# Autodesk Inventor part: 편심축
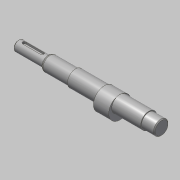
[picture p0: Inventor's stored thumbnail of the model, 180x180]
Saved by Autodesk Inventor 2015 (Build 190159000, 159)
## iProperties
Created: 2017-08
Part Number: 편심축
Material: 강철, 연강
Document SubType Name: Modeling
Designer: mduedu
Density: 1 g/cm^3
Appearance: 강철
Author: mduedu
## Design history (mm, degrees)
sketch "스케치1"
  geometry: L1 (0, 0)-(168, 0); L2 (168, 0)-(168, 8.5); L3 (168, 8.5)-(153, 8.5); L4 (153, 8.5)-(153, 9.5); L5 (153, 9.5)-(67, 9.5); L6 (67, 9.5)-(67, 8.5); L7 (67, 8.5)-(35, 8.5); L8 (35, 8.5)-(35, 6); L9 (35, 6)-(0, 6); L10 (0, 6)-(0, 0)
  constraints: 20 end point, 6 parallel, 2 collinear, 2 perpendicular, 1 horizontal
  dimensions: "d0" = 168 distance of L1.start L1.end; "d1" = 17 diameter of L3 L1; "d2" = 19 diameter of L5 L1; "d3" = 12 diameter of L9 L1; "d4" = 35 distance of L8.end L9.end; "d5" = 15 distance of L2.end L3.end; "d6" = 86 distance of L4.end L5.end
revolve "회전1" sketch "스케치1" stored, may be unused: angle "d7" = 90 deg
node "작업 평면1"
sketch "스케치2"
  geometry: C1 r 9.5 at (0, 0) reference; C2 r 13 at (0, -3.5); 1 further point
  constraints: 1 centre point, 1 tangent, 1 vertical alignment
  dimensions: "d8" = 3.5 distance of point (0, 0) C2.centre
extrude "돌출1" join sketch "스케치2" stored distance "d9" = 18; taper "d10" = 0 deg
chamfer "모따기1" distance "d11" = 1; stored, may be unused: second distance "d12" = 2, angle "d13" = 45 deg
node "작업 평면2"
sketch "스케치3"
  geometry: L1 (10.5, -2)-(-10.5, -2); L2 (-10.5, -2)-(-10.5, 2); L3 (-10.5, 2)-(10.5, 2); L4 (10.5, 2)-(10.5, -2); L5 (17.5, 6)-(17.5, -6) reference; L6 (-17.5, 8.5)-(-17.5, -8.5) reference; A1 r 2 centre (10.5, 0) between (10.5, -2) and (10.5, 2); A2 r 2 centre (-10.5, 0) between (-10.5, 2) and (-10.5, -2); A3 r 2 centre (10.5, 0) between (10.5, 2) and (10.5, -2); A4 r 2 centre (-10.5, 0) between (-10.5, -2) and (-10.5, 2); 1 further point
  constraints: 8 end point, 8 point on circle, 4 centre point, 2 midpoint, 2 parallel, 1 horizontal, 1 horizontal alignment, 1 perpendicular
  dimensions: "d14" = 25 dimension on A2 A1; "d16" = 4 distance between parallel lines of L3 L1; "d17" = 5 distance edge to line of A1 L5; "d46" = 5 distance edge to line of A2 L6 (derived)
extrude "돌출2" cut sketch "스케치3" distance "d18" = 2.5; taper "d19" = 0 deg
chamfer "모따기2" distance "d20" = 1; stored, may be unused: second distance "d21" = 2, angle "d22" = 45 deg
chamfer "모따기4" distance "d39" = 1.82; stored, may be unused: second distance "d40" = 2, angle "d41" = 30 deg
fillet "모깎기4" dims "d45" = 2
hole "구멍1" diameter "d29" = 3.242; stored, may be unused: countersink angle "d33" = 90 deg, drill point angle "d35" = 118 deg; dims "d30" = 8, "d31" = 4, "d32" = 2, "d34" = 10, "d36" = 10, "d37" = 10
node "솔리드1"
node "절단 모서리 투영1"
